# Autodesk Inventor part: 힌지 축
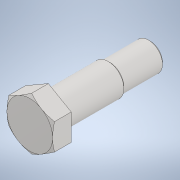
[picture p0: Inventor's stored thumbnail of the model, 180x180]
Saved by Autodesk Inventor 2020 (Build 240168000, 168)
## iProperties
Created: 2024-04
Part Number: 힌지 축
Material: 스테인리스강
Document SubType Name: Modeling
Designer: oem
Density: 8.08 g/cm^3
Appearance: 기본값
Author: jhkim
Sending System: Autodesk Inventor 2025
Preprocessor: ST-DEVELOPER v20
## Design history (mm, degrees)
feature "솔리드1"
node "솔리드2"
